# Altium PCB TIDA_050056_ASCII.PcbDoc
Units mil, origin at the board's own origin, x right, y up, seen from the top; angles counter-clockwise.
Board outline 780 x 850 mil, 4 copper layers (Top Layer, Signal Layer 1, Signal Layer 2, Bottom Layer), stack 40 mil thick; 23 components, 6 nets, 30 pads, 38 vias.
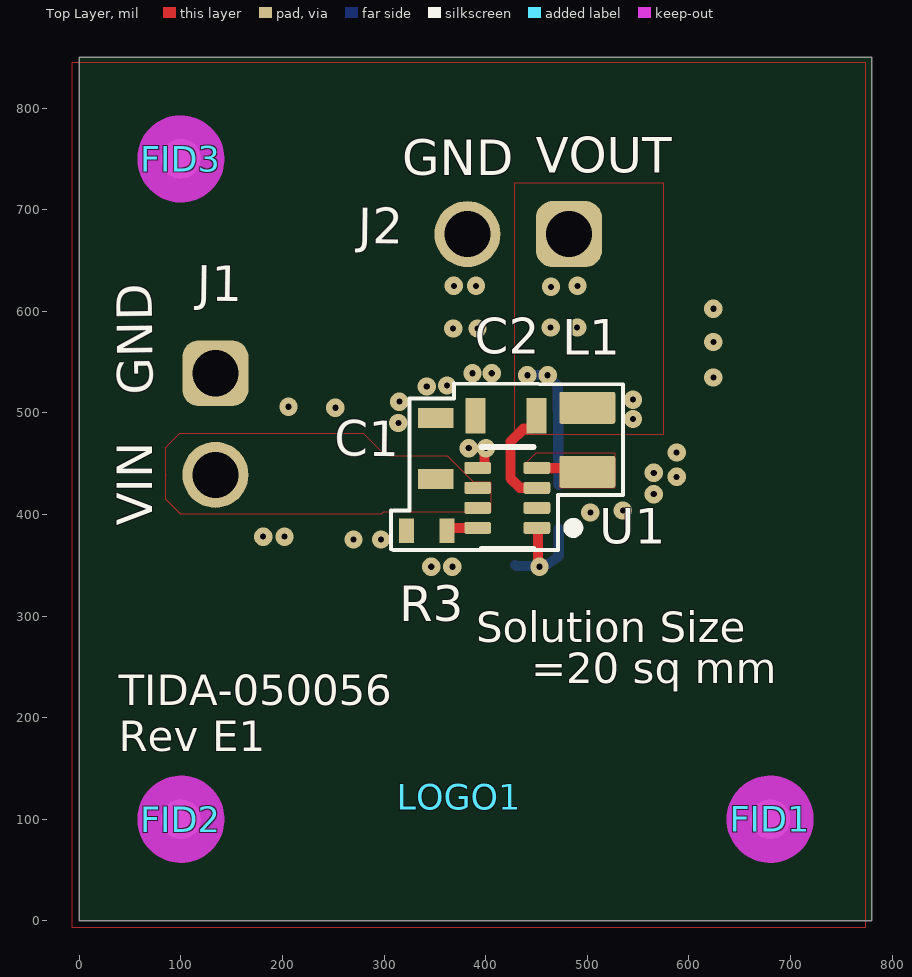
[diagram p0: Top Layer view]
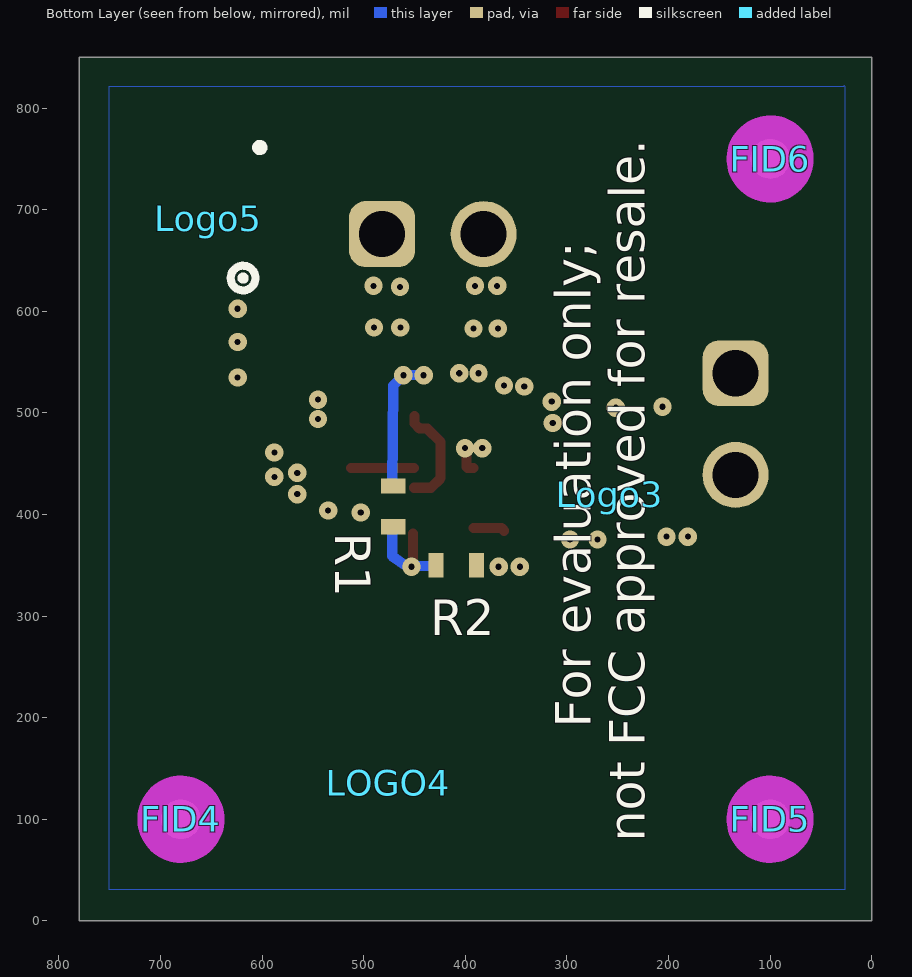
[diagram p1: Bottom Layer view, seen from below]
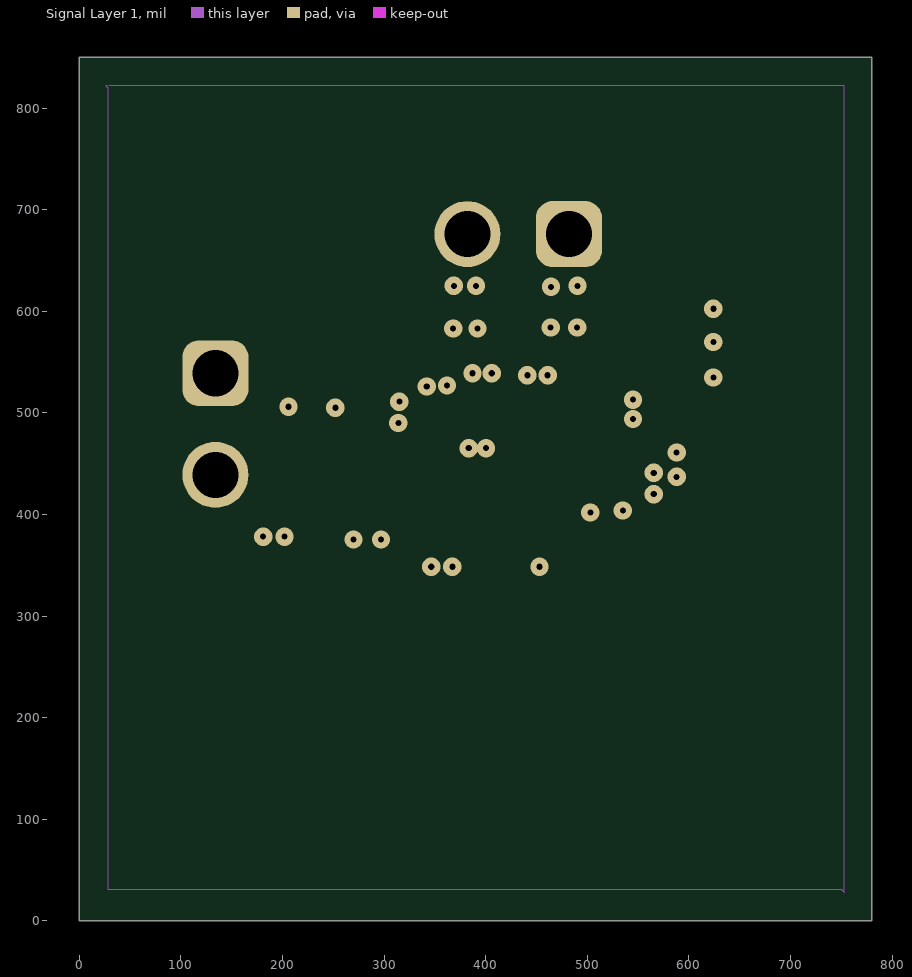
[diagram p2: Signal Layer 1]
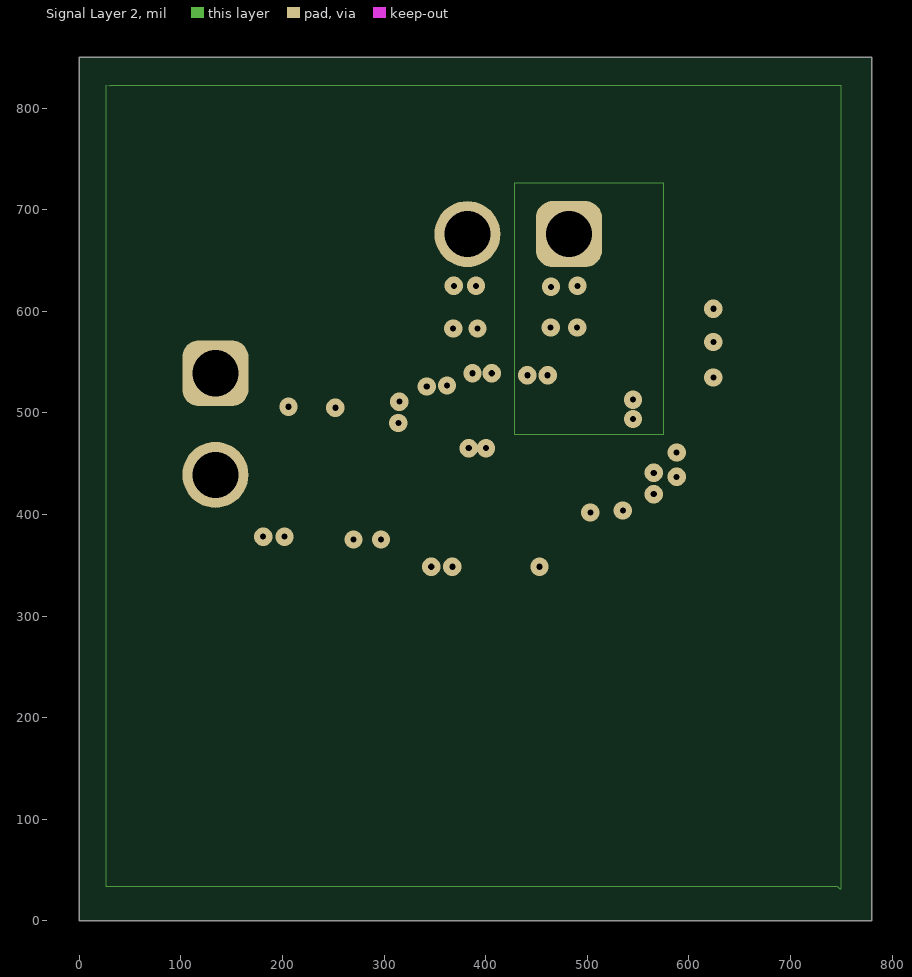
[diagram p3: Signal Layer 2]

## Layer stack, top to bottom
Top Solder: solder mask 0.4, Solder Resist, Dk 3.5
Top Layer: signal copper 1.4
Dielectric 1: prepreg 5, FR-4 High Tg, Dk 4.2
Signal Layer 1: signal copper 1.4
Dielectric 2: core 24.4, FR-4 High Tg, Dk 4.2
Signal Layer 2: signal copper 1.4
Dielectric 3: prepreg 5, FR-4 High Tg, Dk 4.2
Bottom Layer: signal copper 1.4
Bottom Solder: solder mask 0.4, Solder Resist, Dk 3.5

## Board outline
0,0 780,0 780,850 0,850

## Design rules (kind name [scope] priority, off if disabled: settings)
AcuteAngle [All] p0: scope1count=1 scope1_0_kind=Board scope1_0_value=Board scope2count=1 scope2_0_kind=Board scope2_0_value=Board commentlength=0 minimum=4.50000000000000E+0001
AcuteAngle [All] p1: minimum=4.50000000000000E+0001 checktracksonly=FALSE
AssemblyTestPointUsage [All] p0: scope1count=1 scope1_0_kind=Board scope1_0_value=Board scope2count=1 scope2_0_kind=Board scope2_0_value=Board commentlength=0
AssemblyTestPointUsage [All] p1: valid=2
AssemblyTestpoint [All] p0: scope1count=1 scope1_0_kind=Board scope1_0_value=Board scope2count=1 scope2_0_kind=Board scope2_0_value=Board commentlength=0
BoardOutlineClearance BoardOutlineClearance_MountingHoles [All] p0 off: scope1count=1 scope1_0_kind=Board scope1_0_value=Board scope2count=1 scope2_0_kind=Board scope2_0_value=Board commentlength=86 gap=40 // Protel DXP Scope 1 Expression Was: OnCopper and InComponentClass('Mounting Holes')
BoardOutlineClearance BoardOutlineClearance_Poly [All] p0 off: scope1count=1 scope1_0_kind=Board scope1_0_value=Board scope2count=1 scope2_0_kind=Board scope2_0_value=Board commentlength=58 gap=25 // Protel DXP Scope 1 Expression Was: OnCopper and IsPoly
BoardOutlineClearance [All] p0 off: scope1count=1 scope1_0_kind=Board scope1_0_value=Board scope2count=1 scope2_0_kind=Board scope2_0_value=Board commentlength=172 gap=40 // Protel DXP Scope 1 Expression Was: OnCopper and Not InComponentClass('Logo') and not InComponentClass('FiducialMark') and not InRegion(1000,500,4000,800) and not InPoly
BoardOutlineClearance BoardOutlineClearance_MountingHoles [OnCopper and InComponentClass('Mounting Holes')] p1: gap=40 ignorepadtopadclearanceinfootprint=FALSE
BoardOutlineClearance BoardOutlineClearance_Poly [OnCopper and IsPoly] p2: gap=25 ignorepadtopadclearanceinfootprint=FALSE
BoardOutlineClearance [OnCopper and Not InComponentClass('Logo') and not InComponentClass('FiducialMark') and not InRegion(1000,500,4000,800) and not InPoly] p3: gap=40 ignorepadtopadclearanceinfootprint=FALSE
Clearance Clearance_Keepouts [All] p0 off: scope1count=1 scope1_0_kind=Board scope1_0_value=Board scope2count=1 scope2_0_kind=Board scope2_0_value=Board commentlength=99 gap=0 // Protel DXP Scope 2 Expression Was: ((IsTrack Or IsArc) And Not InPoly) And IsFree and IsKeepOut
Clearance Clearance_Poly [All] p0 off: scope1count=1 scope1_0_kind=Board scope1_0_value=Board scope2count=1 scope2_0_kind=Board scope2_0_value=Board commentlength=48 gap=10 // Protel DXP Scope 1 Expression Was: InPolygon
Clearance Clearance_FiducialMark [All] p0 off: scope1count=1 scope1_0_kind=Board scope1_0_value=Board scope2count=1 scope2_0_kind=Board scope2_0_value=Board commentlength=81 gap=0 // Protel DXP Scope 2 Expression Was: IsPad and InComponentClass('FiducialMark')
Clearance [All] p0: scope1count=1 scope1_0_kind=Board scope1_0_value=Board scope2count=1 scope2_0_kind=Board scope2_0_value=Board commentlength=0 gap=7.87
Clearance Clearance_Keepouts [((IsTrack Or IsArc) And Not InPoly) And IsFree and IsKeepOut vs ((IsTrack Or IsArc) And Not InPoly) And IsFree and IsKeepOut] p1: gap=0 ignorepadtopadclearanceinfootprint=FALSE
Clearance Clearance_Poly [InPolygon] p2: gap=10 ignorepadtopadclearanceinfootprint=FALSE
Clearance Clearance_FiducialMark [IsKeepOut and InComponentClass('FiducialMark') vs IsPad and InComponentClass('FiducialMark')] p3: gap=0 ignorepadtopadclearanceinfootprint=FALSE
Clearance [All] p4: gap=7.87 ignorepadtopadclearanceinfootprint=FALSE
ComponentClearance ComponentClearance_MountingHoles_FiducialMarks [All] p0: scope1count=1 scope1_0_kind=ComponentClass scope1_0_value="Mounting Holes" scope2count=1 scope2_0_kind=ComponentClass scope2_0_value=FiducialMark commentlength=0 gap=50 collisioncheckmode=3
ComponentClearance ComponentClearance_Shunt [All] p0: scope1count=1 scope1_0_kind=ComponentClass scope1_0_value=Header scope2count=1 scope2_0_kind=ComponentClass scope2_0_value=Shunt commentlength=0 gap=0 collisioncheckmode=3
ComponentClearance ComponentClearance_Logo [All] p0: scope1count=1 scope1_0_kind=ComponentClass scope1_0_value=Logo scope2count=1 scope2_0_kind=Board scope2_0_value=Board commentlength=0 gap=30 collisioncheckmode=3
ComponentClearance ComponentClearance_ScrewToNut [All] p0 off: scope1count=1 scope1_0_kind=Board scope1_0_value=Board scope2count=1 scope2_0_kind=Board scope2_0_value=Board commentlength=71 gap=5 collisioncheckmode=3 // Protel DXP Scope 2 Expression Was: (HasFootprint('Keystone_1902C'))
ComponentClearance ComponentClearance_MountingHoles [All] p0: scope1count=1 scope1_0_kind=ComponentClass scope1_0_value="Mounting Holes" scope2count=1 scope2_0_kind=Board scope2_0_value=Board commentlength=0 gap=100 collisioncheckmode=3
ComponentClearance ComponentClearance_SmallPassives [All] p0 off: scope1count=1 scope1_0_kind=Board scope1_0_value=Board scope2count=1 scope2_0_kind=Board scope2_0_value=Board commentlength=508 gap=14.96 collisioncheckmode=3 // Protel DXP Scope 2 Expression Was: HasFootprint('0201*') or HasFootprint('0402*') or HasFootprint('0508') or HasFootprint('0603*') or HasFootprint('0612') or HasFootprint('0805*') or HasFootprint('0815*') or HasFootprint('0830*') or HasFootprint('1206*') or HasFootprint('1210*') or HasFootprint('1808*') or HasFootprint('1812*') or HasFootprint('1825*') or HasFootprint('2010*') or HasFootprint('2220*') or HasFootprint('2225*') or HasFootprint('2512*') or HasFootprint('2728*') or HasFootprint('3518*')
ComponentClearance ComponentClearance_THtoSMT [All] p0 off: scope1count=1 scope1_0_kind=Board scope1_0_value=Board scope2count=1 scope2_0_kind=Board scope2_0_value=Board commentlength=53 gap=30 collisioncheckmode=3 // Protel DXP Scope 2 Expression Was: IsSMTComponent
ComponentClearance ComponentClearance_THtoTH [All] p0 off: scope1count=1 scope1_0_kind=Board scope1_0_value=Board scope2count=1 scope2_0_kind=Board scope2_0_value=Board commentlength=54 gap=30 collisioncheckmode=3 // Protel DXP Scope 2 Expression Was: IsThruComponent
ComponentClearance [All] p0: scope1count=1 scope1_0_kind=Board scope1_0_value=Board scope2count=1 scope2_0_kind=Board scope2_0_value=Board commentlength=0 gap=20 collisioncheckmode=3
ComponentClearance ComponentClearance_MountingHoles_FiducialMarks [InComponentClass('Mounting Holes') vs InComponentClass('FiducialMark')] p1: gap=50 collisioncheckmode=3 verticalgap=10 showdistances=FALSE
ComponentClearance ComponentClearance_Shunt [InComponentClass('Header') vs InComponentClass('Shunt')] p2: gap=0 collisioncheckmode=3 verticalgap=0 showdistances=FALSE
ComponentClearance ComponentClearance_Logo [InComponentClass('Logo')] p3: gap=30 collisioncheckmode=3 verticalgap=10 showdistances=FALSE
ComponentClearance ComponentClearance_ScrewToNut [(HasFootprint('NY PMS 440 0025 PH')) vs (HasFootprint('Keystone_1902C'))] p4: gap=5 collisioncheckmode=3 verticalgap=10 showdistances=FALSE
ComponentClearance ComponentClearance_MountingHoles [InComponentClass('Mounting Holes')] p5: gap=100 collisioncheckmode=3 verticalgap=100000 showdistances=FALSE
ComponentClearance ComponentClearance_SmallPassives [HasFootprint('0201*') or HasFootprint('0402*') or HasFootprint('0508') or HasFootprint('0603*') or HasFootprint('0612') or HasFootprint('0805*') or HasFootprint('0815*') or HasFootprint('0830*') or HasFootprint('1206*') or HasFootprint('1210*') or HasFootprint('1808*') or HasFootprint('1812*') or HasFootprint('1825*') or HasFootprint('2010*') or HasFootprint('2220*') or HasFootprint('2225*') or HasFootprint('2512*') or HasFootprint('2728*') or HasFootprint('3518*') vs HasFootprint('0201*') or HasFootprint('0402*') or HasFootprint('0508') or HasFootprint('0603*') or HasFootprint('0612') or HasFootprint('0805*') or HasFootprint('0815*') or HasFootprint('0830*') or HasFootprint('1206*') or HasFootprint('1210*') or HasFootprint('1808*') or HasFootprint('1812*') or HasFootprint('1825*') or HasFootprint('2010*') or HasFootprint('2220*') or HasFootprint('2225*') or HasFootprint('2512*') or HasFootprint('2728*') or HasFootprint('3518*')] p6: gap=14.96 collisioncheckmode=3 verticalgap=10 showdistances=FALSE
ComponentClearance ComponentClearance_THtoSMT [IsThruComponent vs IsSMTComponent] p7: gap=30 collisioncheckmode=3 verticalgap=30 showdistances=FALSE
ComponentClearance ComponentClearance_THtoTH [IsThruComponent vs IsThruComponent] p8: gap=30 collisioncheckmode=3 verticalgap=30 showdistances=FALSE
ComponentClearance [All] p9: gap=20 collisioncheckmode=3 verticalgap=10 showdistances=FALSE
DiffPairsRouting [All] p0: scope1count=1 scope1_0_kind=Board scope1_0_value=Board scope2count=1 scope2_0_kind=Board scope2_0_value=Board commentlength=0
DiffPairsRouting [All] p1: maxlimit=100 minlimit=10 mostfreqgap=10 toplayer_minwidth=15 toplayer_maxwidth=15 toplayer_prefwidth=15 midlayer1_minwidth=15 midlayer1_maxwidth=15 midlayer1_prefwidth=15 midlayer2_minwidth=15 midlayer2_maxwidth=15 midlayer2_prefwidth=15 bottomlayer_minwidth=15 bottomlayer_maxwidth=15 bottomlayer_prefwidth=15 maxuncoupledlength=1000
FabricationTestPointUsage TestPointUsage [All] p0: scope1count=1 scope1_0_kind=Board scope1_0_value=Board scope2count=1 scope2_0_kind=Board scope2_0_value=Board commentlength=0 valid=2 allowmultiple=FALSE
FabricationTestPointUsage TestPointUsage [All] p1: valid=2 allowmultiple=FALSE
FabricationTestpoint Testpoint [All] p0: scope1count=1 scope1_0_kind=Board scope1_0_value=Board scope2count=1 scope2_0_kind=Board scope2_0_value=Board commentlength=0 side=3 testpointundercomponent=TRUE minsize=40 maxsize=100 preferedsize=60 minholesize=0 maxholesize=40 preferedholesize=32 testpointgrid=1
FabricationTestpoint Testpoint [All] p1: side=3 testpointundercomponent=TRUE minsize=40 maxsize=100 preferedsize=60 minholesize=0 maxholesize=40 preferedholesize=32 testpointgrid=1 allowsidetop=TRUE allowsidebottom=TRUE usegrid=TRUE gridtolerance=0.01
FanoutControl Fanout_LCC [All] p0 off: scope1count=1 scope1_0_kind=Board scope1_0_value=Board scope2count=1 scope2_0_kind=Board scope2_0_value=Board commentlength=69 // Protel DXP Scope 1 Expression Was: IsLCC   Fanout_LCC (Default Rule)
FanoutControl Fanout_BGA [All] p0 off: scope1count=1 scope1_0_kind=Board scope1_0_value=Board scope2count=1 scope2_0_kind=Board scope2_0_value=Board commentlength=69 // Protel DXP Scope 1 Expression Was: IsBGA   Fanout_BGA (Default Rule)
FanoutControl Fanout_SOIC [All] p0 off: scope1count=1 scope1_0_kind=Board scope1_0_value=Board scope2count=1 scope2_0_kind=Board scope2_0_value=Board commentlength=71 // Protel DXP Scope 1 Expression Was: IsSOIC   Fanout_SOIC (Default Rule)
FanoutControl Fanout_Default [All] p0: scope1count=1 scope1_0_kind=Board scope1_0_value=Board scope2count=1 scope2_0_kind=Board scope2_0_value=Board commentlength=30 // Fanout_Default (Default Rule)
FanoutControl Fanout_Small [All] p0 off: scope1count=1 scope1_0_kind=Board scope1_0_value=Board scope2count=1 scope2_0_kind=Board scope2_0_value=Board commentlength=84 // Protel DXP Scope 1 Expression Was: (CompPinCount < 5)   Fanout_Small (Default Rule)
FanoutControl Fanout_LCC [IsLCC] p1: bgadir=Out bgaviamode=Centered fanoutstyle=Auto fanoutdirection=Alternating viagrid=1 // Fanout_LCC (Default Rule)
FanoutControl Fanout_BGA [IsBGA] p2: bgadir=Out bgaviamode=Centered fanoutstyle=Auto fanoutdirection=Alternating viagrid=1 // Fanout_BGA (Default Rule)
FanoutControl Fanout_Default [All] p4: bgadir=Out bgaviamode=Centered fanoutstyle=Auto fanoutdirection=Alternating viagrid=1 // Fanout_Default (Default Rule)
FanoutControl Fanout_Small [(CompPinCount < 5)] p5: bgadir=Out bgaviamode=Centered fanoutstyle=Auto fanoutdirection=OutThenIn viagrid=1 // Fanout_Small (Default Rule)
Height [All] p0: scope1count=1 scope1_0_kind=Board scope1_0_value=Board scope2count=1 scope2_0_kind=Board scope2_0_value=Board commentlength=0
HoleSize [All] p0: scope1count=1 scope1_0_kind=Board scope1_0_value=Board scope2count=1 scope2_0_kind=Board scope2_0_value=Board commentlength=0 absolutevalues=TRUE maxlimit=251 minlimit=5.9 maxpercent=80.000 minpercent=20.000
HoleSize [All] p1: absolutevalues=TRUE maxlimit=251 minlimit=5.9 maxpercent=80.000 minpercent=20.000
HoleToHoleClearance [All] p0: scope1count=1 scope1_0_kind=Board scope1_0_value=Board scope2count=1 scope2_0_kind=Board scope2_0_value=Board commentlength=0
LayerPairs [All] p0: scope1count=1 scope1_0_kind=Board scope1_0_value=Board scope2count=1 scope2_0_kind=Board scope2_0_value=Board commentlength=0 enforce=TRUE
MinimumAnnularRing MinimumAnnularRing_ThermalPadVias [All] p0 off: scope1count=1 scope1_0_kind=Board scope1_0_value=Board scope2count=1 scope2_0_kind=Board scope2_0_value=Board commentlength=63 minimumring=5.91 // Protel DXP Scope 1 Expression Was: IsVia and InAnyComponent
MinimumAnnularRing [All] p0: scope1count=1 scope1_0_kind=Board scope1_0_value=Board scope2count=1 scope2_0_kind=Board scope2_0_value=Board commentlength=0 minimumring=6
MinimumAnnularRing MinimumAnnularRing_ThermalPadVias [IsVia and InAnyComponent] p1: minimumring=5.91
MinimumAnnularRing [All] p2: minimumring=6
MinimumSolderMaskSliver MinimumSolderMaskSliver_Logo [All] p0: scope1count=1 scope1_0_kind=ComponentClass scope1_0_value=Logo scope2count=1 scope2_0_kind=ComponentClass scope2_0_value=Logo commentlength=0
MinimumSolderMaskSliver [All] p0: scope1count=1 scope1_0_kind=Board scope1_0_value=Board scope2count=1 scope2_0_kind=Board scope2_0_value=Board commentlength=0
MinimumSolderMaskSliver MinimumSolderMaskSliver_Logo [InComponentClass('Logo') vs InComponentClass('Logo')] p1: minsoldermaskwidth=0.7
MinimumSolderMaskSliver [All] p2: minsoldermaskwidth=3.94
NetAntennae [All] p0: scope1count=1 scope1_0_kind=Board scope1_0_value=Board scope2count=1 scope2_0_kind=Board scope2_0_value=Board commentlength=0
PasteMaskExpansion [All] p0: scope1count=1 scope1_0_kind=Board scope1_0_value=Board scope2count=1 scope2_0_kind=Board scope2_0_value=Board commentlength=0 expansion=0
PlaneClearance [All] p0: scope1count=1 scope1_0_kind=Board scope1_0_value=Board scope2count=1 scope2_0_kind=Board scope2_0_value=Board commentlength=0 clearance=20
PlaneConnect [All] p0: scope1count=1 scope1_0_kind=Board scope1_0_value=Board scope2count=1 scope2_0_kind=Board scope2_0_value=Board commentlength=0 planeconnectstyle=Relief reliefexpansion=10 reliefentries=4 reliefconductorwidth=10 reliefairgap=10
PlaneConnect [All] p1: planeconnectstyle=Relief reliefexpansion=10 reliefentries=4 reliefconductorwidth=10 reliefairgap=10
PolygonConnect [All] p0: scope1count=1 scope1_0_kind=Board scope1_0_value=Board scope2count=1 scope2_0_kind=Board scope2_0_value=Board commentlength=0 connectstyle=Direct reliefconductorwidth=10 reliefentries=4 polygonreliefangle="90 Angle"
PolygonConnect PolygonConnect_R2 [All] p0 off: scope1count=1 scope1_0_kind=Board scope1_0_value=Board scope2count=1 scope2_0_kind=Board scope2_0_value=Board commentlength=140 connectstyle=Relief reliefconductorwidth=10 reliefentries=4 polygonreliefangle="90 Angle" // Protel DXP Scope 1 Expression Was: InComponent('R4') or InComponent('C3') or InComponent('R2') or InComponent('R6') or InComponent('R8')
PolygonConnect PolygonConnect_R2 [InComponent('R4') or InComponent('C3') or InComponent('R2') or InComponent('R6') or InComponent('R8')] p1: connectstyle=Relief reliefconductorwidth=10 reliefentries=4 polygonreliefangle="90 Angle" airgapwidth=10
PolygonConnect [All] p2: connectstyle=Direct reliefconductorwidth=10 reliefentries=4 polygonreliefangle="90 Angle" airgapwidth=10
RoutingCorners [All] p0: scope1count=1 scope1_0_kind=Board scope1_0_value=Board scope2count=1 scope2_0_kind=Board scope2_0_value=Board commentlength=0 cornerstyle=45-Degree minsetback=100 maxsetback=100
RoutingLayers [All] p0: scope1count=1 scope1_0_kind=Board scope1_0_value=Board scope2count=1 scope2_0_kind=Board scope2_0_value=Board commentlength=0 top layer=Automatic mid layer 1=Automatic mid layer 2=Automatic bottom layer=Automatic
RoutingPriority [All] p0: scope1count=1 scope1_0_kind=Board scope1_0_value=Board scope2count=1 scope2_0_kind=Board scope2_0_value=Board commentlength=0
RoutingTopology [All] p0: scope1count=1 scope1_0_kind=Board scope1_0_value=Board scope2count=1 scope2_0_kind=Board scope2_0_value=Board commentlength=0 topology=Shortest
RoutingVias ThermalPadVias [All] p0 off: scope1count=1 scope1_0_kind=Board scope1_0_value=Board scope2count=1 scope2_0_kind=Board scope2_0_value=Board commentlength=63 holewidth=7.87 width=19.68 viastyle="Through Hole" minholewidth=7.87 minwidth=19.68 maxholewidth=12.99 maxwidth=23.62 // Protel DXP Scope 1 Expression Was: IsVia and InAnyComponent
RoutingVias [All] p0: scope1count=1 scope1_0_kind=Board scope1_0_value=Board scope2count=1 scope2_0_kind=Board scope2_0_value=Board commentlength=0 holewidth=16 width=34 viastyle="Through Hole" minholewidth=5.9 minwidth=18 maxholewidth=40 maxwidth=65
RoutingVias ThermalPadVias [IsVia and InAnyComponent] p1: holewidth=7.87 width=19.68 viastyle="Through Hole" minholewidth=7.87 minwidth=19.68 maxholewidth=12.99 maxwidth=23.62
RoutingVias [All] p2: holewidth=16 width=34 viastyle="Through Hole" minholewidth=5.9 minwidth=18 maxholewidth=40 maxwidth=65
ShortCircuit [All] p0: scope1count=1 scope1_0_kind=Board scope1_0_value=Board scope2count=1 scope2_0_kind=Board scope2_0_value=Board commentlength=0 allowed=FALSE
SilkToBoardRegionClearance [All] p0 off: scope1count=1 scope1_0_kind=Board scope1_0_value=Board scope2count=1 scope2_0_kind=Board scope2_0_value=Board commentlength=130 // Protel DXP Scope 1 Expression Was: Not ((IsComment or IsDesignator) And (Hide <> 'False')) and not InRegion(1000,500,4000,800)
SilkToBoardRegionClearance [Not ((IsComment or IsDesignator) And (Hide <> 'False')) and not InRegion(1000,500,4000,800)] p1:
SilkToSilkClearance SilkToSilkClearance_Pb-FreeLogo [All] p0 off: scope1count=1 scope1_0_kind=Board scope1_0_value=Board scope2count=1 scope2_0_kind=Board scope2_0_value=Board commentlength=120 // Protel DXP Scope 2 Expression Was: (HasFootprint('Pb-Free_Overlay_Medium') OR HasFootprint('Pb-Free_Overlay_Small'))
SilkToSilkClearance [All] p0: scope1count=1 scope1_0_kind=Board scope1_0_value=Board scope2count=1 scope2_0_kind=Board scope2_0_value=Board commentlength=0
SilkToSilkClearance SilkToSilkClearance_Pb-FreeLogo [(HasFootprint('Pb-Free_Overlay_Medium') OR HasFootprint('Pb-Free_Overlay_Small')) vs (HasFootprint('Pb-Free_Overlay_Medium') OR HasFootprint('Pb-Free_Overlay_Small'))] p1: silktosilkclearance=0
SilkToSilkClearance [All] p2: silktosilkclearance=4
SilkToSolderMaskClearance SilkToComponentPadClearance [All] p0 off: scope1count=1 scope1_0_kind=Board scope1_0_value=Board scope2count=1 scope2_0_kind=Board scope2_0_value=Board commentlength=87 // Protel DXP Scope 1 Expression Was: (IsPad or IsFill or IsRegion) and InAnycomponent
SilkToSolderMaskClearance "Silk to Solder Mask Opening" [All] p0: scope1count=1 scope1_0_kind=Board scope1_0_value=Board scope2count=1 scope2_0_kind=Board scope2_0_value=Board commentlength=0
SilkToSolderMaskClearance SilkToComponentPadClearance [(IsPad or IsFill or IsRegion) and InAnycomponent] p1: minsilkscreentomaskgap=5 clearancetoexposedcopper=TRUE
SilkToSolderMaskClearance "Silk to Solder Mask Opening" [All] p2: minsilkscreentomaskgap=3.94 clearancetoexposedcopper=FALSE
SolderMaskExpansion [All] p0: scope1count=1 scope1_0_kind=Board scope1_0_value=Board scope2count=1 scope2_0_kind=Board scope2_0_value=Board commentlength=0 expansion=1.97
SolderMaskExpansion [All] p1: expansion=1.97 istentingtop=FALSE
UnRoutedNet [All] p0: scope1count=1 scope1_0_kind=Board scope1_0_value=Board scope2count=1 scope2_0_kind=Board scope2_0_value=Board commentlength=0
UnpouredPolygon [All] p0: scope1count=1 scope1_0_kind=Board scope1_0_value=Board scope2count=1 scope2_0_kind=Board scope2_0_value=Board commentlength=0
Width [All] p0: scope1count=1 scope1_0_kind=Board scope1_0_value=Board scope2count=1 scope2_0_kind=Board scope2_0_value=Board commentlength=0 maxlimit=100 minlimit=6 preferedwidth=10
Width [All] p1: maxlimit=100 minlimit=6 preferedwidth=10 checkconnectedcopper=TRUE
15 further rules are at their usual default settings.

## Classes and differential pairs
component class Logo: LOGO1
component class TIDA_050056_Hardware: FID1 FID2 FID3 FID4 FID5 FID6 LOGO1 Logo3 LOGO4 Logo5 SH-J1 SH-J5 ZZ1 ZZ2 ZZ3 ZZ4
component class FiducialMark: FID1 FID2 FID3 FID4 FID5 FID6
component class AssemblyNote: ZZ1 ZZ2 ZZ3 ZZ4
component class TIDA_050056: C1 C2 J1 J2 L1 R1 R2 R3 R49 U1
component class Header: J1 J2

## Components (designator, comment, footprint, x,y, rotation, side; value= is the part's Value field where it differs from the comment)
C1 "GRM188R61E106MA73D" 0603S 351,465 r90 top
C2 "GRM188R61A226ME15D" 0603S 420,497 r180 top
FID1 "Fiducial" Fiducial10-20 680,100 r0 top
FID2 "Fiducial" Fiducial10-20 100,100 r0 top
FID3 "Fiducial" Fiducial10-20 100,750 r0 top
FID4 "Fiducial" Fiducial10-20 680,100 r90 bottom
FID5 "Fiducial" Fiducial10-20 100,100 r180 bottom
FID6 "Fiducial" Fiducial10-20 100,750 r180 bottom
J1 "61300211121" WURTH_61300211121 134,489 r270 top
J2 "61300211121" WURTH_61300211121 432,676 r180 top
L1 "DFE201210U-1R5M=P2" "FP-DFE201210U-1R5M=P2_0805 (2012)-MFG" 500,473.5 r90 top
LOGO1 "Texas Instruments" TI_Symbol_Overlay_Small 374,122 r0 top
Logo3 "FCC disclaimer" FCC_disclaimer_stacked 258,420 r90 bottom
LOGO4 "CE Mark" CE_Mark_5mm 476,136 r180 bottom
Logo5 "WEEE logo" WEEE_Minimum 652.92,691 r180 bottom
R1 "CRCW0402154KFKED" 0402S 471,408 r90 bottom
R2 "CRCW040234K0FKED" 0402S 409.01,350.11 r0 bottom
R3 "CRCW040227K4FKED" 0402S 342,384 r0 top
U1 "TPS629210QDRLRQ1" DRL0008A-MFG 421.26,416.34 r180 top
ZZ1 "This Assembly Note is for PCB labels only" AssemblyNoteLabel 0,1250 r0 top
ZZ2 "These assemblies are ESD sensitive, ESD precautions shall be observed." AssemblyNote 0,1150 r0 top
ZZ3 "These assemblies must be clean and free from flux and all contaminants. Use of no clean flux is not acceptable." AssemblyNote 0,1050 r0 top
ZZ4 "These assemblies must comply with workmanship standards IPC-A-610 Class 2, unless otherwise specified." AssemblyNote 0,950 r0 top

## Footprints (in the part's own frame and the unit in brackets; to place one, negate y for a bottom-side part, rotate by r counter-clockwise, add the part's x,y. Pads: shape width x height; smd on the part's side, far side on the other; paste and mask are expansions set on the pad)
0402S [mil] "Based on C0402S footprint from PADS legacy"
  rect 15x24 smd: 1(-20,0) 2(20,0)
0603S [mil]
  rect 20x35 smd: 1(-30,0) 2(30,0)
AssemblyNote [mil] "Assembly Note"
AssemblyNoteLabel [mil] "Assembly Note for PCB Labels"
CE_Mark_5mm [mil] "Minimum text height for CE Mark"
DRL0008A-MFG [mm]
  rrect33% 0.67x0.3 smd paste+0 mask+0: 1(-0.74,0.75) 2(-0.74,0.25) 3(-0.74,-0.25) 4(-0.74,-0.75) 5(0.74,-0.75) 6(0.74,-0.25) 7(0.74,0.25) 8(0.74,0.75)
  silkscreen extent -1.78,-1.28 0.65,1.28
FCC_disclaimer_stacked [mil]
Fiducial10-20 [mm]
  round 1 smd mask+0: 1(0,0)
  Top Layer keep-out circle w1.178: c0,0 r0.5
"FP-DFE201210U-1R5M=P2_0805 (2012)-MFG" [mm]
  rrect13% 0.8x1.4 smd paste+0 mask+0: 1(-0.8,0) 2(0.8,0)
TI_Symbol_Overlay_Small [mil]
WEEE_Minimum [mil] "WEEElie bin"
  silkscreen extent 22,-71 54,74
WURTH_61300211121 [mm] "Header, 2.54mm, 2x1, TH"
  rrect50% 1.65x1.65 hole 1.15: 1(-1.27,0)
  round 1.65 hole 1.15: 2(1.27,0)

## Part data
C1: library part CMP-0007344-5, "CAP, CERM, 10 uF, 25 V, +/- 20%, X5R, 0603"
C2: library part CMP-0007324-5, "CAP, CERM, 22 uF, 10 V, +/- 20%, X5R, 0603"
FID1 FID2 FID3 FID4 FID5 FID6: library part CMP-0077181-1, "Fiducial mark.  There is nothing to buy or mount."
J1 J2: library part CMP-0054794-2, "Header, 2.54 mm, 2x1, Gold, TH"
L1: library part CMP-0093854-1, "1.5µH Shielded Wirewound Inductor 1.6A 138mOhm Max 0805 (2012 Metric)"
LOGO1: library part CMP-0074838-1, "Texas Instrument Corporate Signature"
Logo3: library part CMP-0074847-1, "FCC_disclaimer"
LOGO4: library part CMP-0074844-1
Logo5: library part CMP-0074769-1
R1: library part CMP-0026023-3, "RES, 154 k, 1%, 0.063 W, AEC-Q200 Grade 0, 0402"
R2: library part CMP-0026304-2, "RES, 34.0 k, 1%, 0.063 W, AEC-Q200 Grade 0, 0402"
R3: library part CMP-0026213-2, "RES, 27.4 k, 1%, 0.063 W, AEC-Q200 Grade 0, 0402"
U1: library part CMP-0089687-1, "3-V to 17-V, Synchronous Buck Converters in 1.6 mm x 2.1 mm SOT583 Package"
ZZ1: library part CMP-0003616-3
ZZ2: library part CMP-0077236-1
ZZ3: library part CMP-0077237-1
ZZ4: library part CMP-0077238-1

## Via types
v1: diameter 18, hole 6, Top Layer to Bottom Layer, tented both sides, 38 vias

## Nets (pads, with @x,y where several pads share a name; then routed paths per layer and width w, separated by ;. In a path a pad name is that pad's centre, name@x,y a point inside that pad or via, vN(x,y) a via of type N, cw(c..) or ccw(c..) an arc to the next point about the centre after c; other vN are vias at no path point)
GND: C1.2 C2.2 J1.1 J2.2 R2.1 R3.1 U1.5 | length 26.2
  Top Layer w10: U1.5 397.88,445.87 398.78,446.77 398.78,463.72 v1(400.32,465.26)
  other v1: 346.41,348.56 367.22,348.56 270,375.27 297.06,375.27 181,378.19 202,378.19 503,402 535,404 565.46,420 588,437 565.46,441 588,461 383.36,465.26 314,490 252,505 206,506 315,511 342,526 362,527 624.09,534.79 387,539 406,539 624.09,569.79 368,583 392,583 624.09,602.5 368.7,625 390.47,625
NetR1_1: R1.1 R2.2 U1.1 | length 99.7
  Top Layer w10: v1@451.59,350.11 U1.1@451.62,381.06
  Bottom Layer w10: R2.2 429.79,349.33 452.13,349.33 v1(452.91,348.56) ; v1@458,349 472,359 R1.1@472,386
NetR3_2: R3.2 U1.8 | length 31.5
  Top Layer w10: R3.2 362,384.31 364.5,386.81 U1.8
SW: L1.1 U1.4 | length 62.1
  Top Layer w10: U1.4 L1.1@512.46,445.87
VIN: C1.1 J1.2 U1.6 U1.7
VOUT: C2.1 J2.1 L1.2 R1.2 U1.3 | length 237.8
  Top Layer w10: C2.1 450,489.5 445,484.5 437.5,484.5 424.33,471.33 424.33,435.77 433.84,426.26 450.31,426.26 U1.3
  Bottom Layer w10: v1@441.8,537.2 460.8,537.2 v1(461,537) v1@463.14,537 ; v1@461.14,536.86 471,527 ; 471,525.14 R1.2@472,429
  other v1: 545,494 545,513 441,537 464,584 490,584 464.31,624 490.31,625
pads on no net: FID1.1 FID2.1 FID3.1 FID4.1 FID5.1 FID6.1 U1.2

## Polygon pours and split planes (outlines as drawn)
GND on Top Layer "TOP_LAYER_GND_P076" (solid, remove dead copper, pour order 76): -6.98,844.96 773.6,844.96 773.6,-6.9 -6.98,-6.9
VIN on Top Layer "TOP_LAYER_VIN_P074" (solid, remove dead copper, pour order 74): 85,438 85,466 99,480 279.44,480 301.44,458 362,458 388,432 404.86,432 404.86,402 299,402 297,400 100,400 85,415 85,439
VOUT on Top Layer "TOP_LAYER_VOUT_P064" (solid, remove dead copper, pour order 64): 427.89,479 575.46,479 575.46,726 427.9,726
SW on Top Layer "TOP_LAYER_SW_P042" (solid, remove dead copper, pour order 42): 437.94,448.94 438,440.84 472.44,440.84 472.44,426.26 527.56,426.26 527.56,460.11 449.11,460.11
GND on Signal Layer 1 "SIGNAL_LAYER_1_GND_P083" (solid, remove dead copper, pour order 83): 26.23,822 28,820.23 28,31 750,31 752.77,28.23 752.77,822 30.5,822 30,822.5
VOUT on Signal Layer 2 "SIGNAL_LAYER_2_VOUT_P087" (solid, remove dead copper, pour order 87): 427.89,479 575.46,479 575.46,726 427.9,726
GND on Signal Layer 2 "SIGNAL_LAYER_2_GND_P088" (solid, remove dead copper, pour order 88): 26.23,822 26.23,34 746,34 749,31 750,32 750,822 30.5,822 30,821.5
GND on Bottom Layer "BOTTOM_LAYER_GND_P082" (solid, remove dead copper, pour order 82): 28,821 751,821 751,31 26.23,31 26.23,821.23 27,822

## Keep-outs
Keep-Out Layer:
  text ".Layer_Name" at 577,-858.49 h60

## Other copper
Top Layer:
  text ".Layer_Name" at 577,-858.49 h60
Signal Layer 1:
  text ".Layer_Name" at 577,-857.49 h60
Signal Layer 2:
  text ".Layer_Name" at 577,-857.49 h60
Bottom Layer:
  text ".Layer_Name" at 577,-858.49 h60

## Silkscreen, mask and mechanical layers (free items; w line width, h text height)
Top Overlay:
  lines w4: 307,366 307,404 ; 309,365 471.16,365 471.09,419 535.29,419 535.29,528.13 369,529.07 369,514 325,514 ; 309,404 324.67,404 ; 325,404 325,513
  text "VOUT" at 449.26,736.34 h35
  text "GND" at 318,734 h35
  text "GND" at 73,518 h35 r90.77
  text "VIN" at 72,389 h35 r90
  text "Solution Size" at 390.48,274 h30
  text "=20 sq mm" at 445,234 h30
  text "TIDA-050056 / Rev E1" at 39,167 h30
  text ".Layer_Name" at 577,-858.49 h60
Bottom Overlay:
  text ".Layer_Name" at 577,-858.49 h60
Top Paste:
  text ".Layer_Name" at 577,-858.49 h60
Bottom Paste:
  text ".Layer_Name" at 577,-858.49 h60
Top Solder:
  text ".Layer_Name" at 577,-858.49 h60
  text ".Layer_Name" at 577,-858.49 h60
Bottom Solder:
  text ".Layer_Name" at 577,-858.49 h60
Drill Guide:
  text ".Layer_Name" at 577,-858.49 h60
M1 Board Outline:
  the board outline again, w10
  text ".Layer_Name" at 577,-858.49 h60
M2 Board Dimensions:
  rectangle: 0,-275 125,-150
  rectangle: 125,-400 500,-275
  lines w7: 0,-275 1000,-275 ; 125,-400 125,-150 ; 250,-400 250,-150 ; 500,-400 500,-150 ; 750,-400 750,-150 ; 0,-400 1000,-400 1000,-150 0,-150 0,-400
  text ".Layer_Name" at 577,-858.49 h60
M3 3D STEP Top:
  text ".Layer_Name" at 577,-858.49 h60
M4 3D STEP Bottom:
  text ".Layer_Name" at 577,-858.49 h60
M5 Assembly Top:
  lines w10: -292,-930.17 6308,-930.17 ; -292,-726.83 6310,-726.83 ; -292,-523.5 -292,-1133.5 3713,-1133.5 6310,-1133.5 6310,-523.5 -291.5,-523.5 -291.5,-1133.5 1284,-1133.5 ; 2173,-1133.5 2173,-523.5 ; 3440,-726.83 3440,-523.5 ; 4280,-726.83 4280,-523.5 ; 4902,-1140 4902,-937.17
  text "COMPONENTS MARKED 'DNP' SHOULD NOT BE POPULATED." at 1153.5,-318.5 h60
  text "ASSEMBLY VARIANT:" at 1153,-434 h60
  text ".VariantName" at 2189,-434 h60
  text "PCB VIEWED FROM TOP SIDE" at -228.5,-655.67 h60
  text "BOARD #:" at 2248,-655.67 h60
  text ".PRJ_Number" at 2793.5,-655.67 h60
  text "REV:" at 3638,-655.67 h60
  text ".PCB_Rev" at 3929.5,-655.67 h60
  text "SVN REV:" at 4476,-655.67 h60
  text ".VersionControl_RevNumber" at 4982,-655.67 h60
  text "TID #:" at 2248,-859 h60
  text ".TID" at 2793.5,-859 h60
  text "PLOT NAME =" at -228.5,-1064.34 h60
  text ".plot_File_Name" at 577,-1064.34 h60
  text "GENERATED    :" at 2250,-1064.34 h60
  text ".Print_Date" at 3119.5,-1064.34 h60
  text ".Print_Time" at 3848.5,-1064.34 h60
  text "TEXAS INSTRUMENTS" at 5113,-1064.34 h60
M6 Assembly Bottom:
  lines w10: -292.5,-727.33 6309.5,-727.33 ; -290.5,-930.67 6309.5,-930.67 ; 1115.5,-1140.5 1115.5,-937.67 ; 1737.5,-727.33 1737.5,-524 ; 2577.5,-727.33 2577.5,-524 ; 3844.5,-1134 3844.5,-524 ; 4733.5,-1134 6309,-1134 6309,-524 -292.5,-524 -292.5,-1134 2304.5,-1134 6309.5,-1134 6309.5,-524
  text "COMPONENTS MARKED 'DNP' SHOULD NOT BE POPULATED." at 6102,-318 h60
  text ".VariantName" at 5058,-434 h60
  text "ASSEMBLY VARIANT:" at 6097,-434 h60
  text ".VersionControl_RevNumber" at 1035.5,-656.17 h60
  text "SVN REV:" at 1541.5,-656.17 h60
  text ".PCB_Rev" at 2088,-656.17 h60
  text "REV:" at 2379.5,-656.17 h60
  text ".PRJ_Number" at 3224,-656.17 h60
  text "BOARD #:" at 3769.5,-656.17 h60
  text "PCB VIEWED FROM BOTTOM SIDE" at 6246,-656.17 h60
  text ".TID" at 3224,-859.5 h60
  text "TID #:" at 3769.5,-859.5 h60
  text "TEXAS INSTRUMENTS" at 904.5,-1064.84 h60
  text ".Print_Time" at 2169,-1064.84 h60
  text ".Print_Date" at 2898,-1064.84 h60
  text "GENERATED    :" at 3767.5,-1064.84 h60
  text ".plot_File_Name" at 5440.5,-1064.84 h60
  text "PLOT NAME =" at 6246,-1064.84 h60
M9 Title Sheet:
  lines w10: -491.5,1041.5 -291.5,1041.5 ; -491.5,3416.5 -291.5,3416.5 ; -491.5,5791.5 -291.5,5791.5 ; 2008.5,-1333.5 2008.5,-1133.5 ; 2008.5,7966.5 2008.5,8166.5 ; 4508.5,-1333.5 4508.5,-1133.5 ; 4508.5,7966.5 4508.5,8166.5 ; 6321,-1133.5 6321,-523.5 11303.5,-523.5 ; 7008.5,-1333.5 7008.5,-1133.5 ; 7008.5,7966.5 7008.5,8166.5 ; 9508.5,-1333.5 9508.5,-1133.5 ; 9508.5,7966.5 9508.5,8166.5 ; 11303.5,-1133.5 11303.5,-523.5 ; 11303.5,-823.5 14303.5,-823.5 ; 11303.5,-223.5 14303.5,-223.5 ; 11304.5,370.5 14304.5,370.5 ; 12008.5,-1333.5 12008.5,-1133.5 ; 12008.5,7966.5 12008.5,8166.5 ; 12808.5,-1123.5 12808.5,-523.5 ; 14303.5,-523.5 11303.5,-523.5 ; 14303.5,76.5 11303.5,76.5 ; 14308.5,66.5 14308.5,-1133.5 ; 14308.5,871 11304.5,871 11303.5,871 11303.5,370.5 11303.5,76.5 ; 14308.5,1041.5 14508.5,1041.5 ; 14308.5,3416.5 14508.5,3416.5 ; 14308.5,5791.5 14508.5,5791.5 ; 11303.5,-523.5 11303.5,76.5 ; 14308.5,-1133.5 14308.5,7966.5 -291.5,7966.5 -291.5,-1133.5 14308.5,-1133.5 ; -491.5,-1333.5 -491.5,8166.5 14508.5,8166.5 14508.5,-1333.5 -491.5,-1333.5
  text "1" at 739.84,8036.5 h70
  text "2" at 3235.5,8036.5 h70
  text "3" at 5724.84,8036.5 h70
  text "4" at 8231.51,8036.5 h70
  text "5" at 10730.5,8036.5 h70
  text "6" at 13235.5,8036.5 h70
  text "A" at -416.5,6893.5 h70
  text "A" at 14383.5,6893.5 h70
  text "B" at -416.5,4513.5 h70
  text "B" at 14383.5,4513.5 h70
  text "C" at -416.5,2138.5 h70
  text "C" at 14383.5,2138.5 h70
  text "PROJECT TITLE:" at 11343.5,277.5 h45
  text ".PRJ_Title" at 11393.5,144.17 h70
  text "DESIGNED FOR:" at 11343.5,-23.5 h45
  text ".PRJ_Customer" at 11393.5,-163.5 h70
  text "D" at -416.5,-231.5 h70
  text "D" at 14383.5,-231.5 h70
  text "FILE NAME:" at 11343.5,-323.5 h45
  text ".PCB_File_Name_No_Path" at 11393.5,-443.5 h70
  text "Texas Instruments (TI) and/or its licensors do not warrant the accuracy or completeness of this specification" at 6374,-605.34 h45
  text "ENGINEER:" at 11343.5,-613.5 h45
  text "LAYOUT BY:" at 12848.5,-613.5 h45
  text "or any information contained therein. TI and/or its licensors do not warrant that this design will meet" at 6329.01,-718 h45
  text ".PRJ_Engineer" at 11393.5,-768.49 h70
  text ".PCB_Layout" at 12899,-768.49 h70
  text "the specifications, will be suitable for your application or fit for any particular purpose, or will operate in" at 6329.01,-830.67 h45
  text ".Layer_Name" at 577,-858.49 h60
  text "ALTIUM DESIGNER VERSION:" at 12848.5,-923.5 h45
  text "an implementation. TI and/or its licensors do not warrant that the design is production worthy. You should" at 6329.01,-943.33 h45
  text "completely validate and test your design implementation to confirm the system functionality for your application." at 6374,-1056 h45
  text ".print_Scale" at 11393.5,-1056.83 h70
  text ".Application_BuildNumber" at 12899,-1056.83 h70
  text "1" at 739.84,-1263.5 h70
  text "2" at 3235.5,-1263.5 h70
  text "3" at 5724.84,-1263.5 h70
  text "4" at 8231.51,-1263.5 h70
  text "5" at 10730.5,-1263.5 h70
  text "6" at 13235.5,-1263.5 h70
M10 Fab Notes:
  drawing of 189 lines, arcs and shapes, not listed
  text "DESIGN INFORMATION" at 12382.02,6356.17 h60
  text "MIN. TRACK WIDTH:" at 11737.46,6224.05 h60
  text "10" at 12833.7,6224.05 h60
  text "MIL" at 12988.46,6224.05 h60
  text "MIN. CLEARANCE:" at 11737.46,6099.92 h60
  text "MIL" at 12988.46,6099.92 h60
  text "7.874" at 12679,6099 h60
  text "MIN. VIA PAD SIZE:" at 11737.46,5975.8 h60
  text "18" at 12803.71,5975.8 h60
  text "MIL" at 12988.46,5975.8 h60
  text "0.05mm (2MIL)" at 12432.46,5845.9 h60
  text "MINIMUM ANNULAR RING" at 11408.23,5837.67 h60
  text "EXTERNAL" at 13140.46,5837.67 h60
  text "PER" at 11608.23,5727.55 h60
  text "IPC-D-275 CLASS 2 LEVEL C" at 11828.23,5727.54 h60
  text "MIL, HOLES" at 13316.46,5627.07 h60
  text "+/-" at 12924,5618.48 h60
  text "+/-" at 13778,5618.48 h60
  text "REGISTRATION TOLERANCES:" at 11408.23,5617.42 h60
  text "METAL" at 12608,5617.42 h60
  text "5" at 13184.2,5617.42 h60
  text "3" at 14017.2,5617.42 h60
  text "MIL" at 14133.46,5617.42 h60
  text "HOLE SIZE TOLERANCE (UNLESS OTHERWISE SPECIFIED):" at 11408.23,5519.1 h60
  text "+/-" at 13778,5516.23 h60
  text "3" at 14017.2,5515.17 h60
  text "MIL" at 14133.46,5515.17 h60
  text "MATERIAL:" at 11333.46,5377.52 h60
  text "FR-4 High Tg" at 12319.9,5249 h60
  text "X" at 12175.46,5241.01 h60
  text "FR-408" at 11754.46,5236.49 h60
  text "OTHER" at 13242.46,5236.49 h60
  text "40 MIL (1.0mm) +/-10%" at 12074.56,5093.46 h60
  text "X" at 11954.46,5091.01 h60
  text "THICKNESS:" at 11408.23,5085.24 h60
  text "OTHER" at 13359.46,5085.24 h60
  text "TOLERANCE:" at 11408.23,4946.92 h60
  text "X" at 12256.46,4946.92 h60
  text "ANSI IPC-6012 TYPE 3 CLASS 2" at 12434.48,4946.92 h60
  text "OTHER +/-" at 12434.46,4802.73 h60
  text "BOW & TWIST:" at 11408.23,4657.54 h60
  text "X" at 12256.46,4657.54 h60
  text "ANSI IPC-6012 TYPE 3 CLASS 2" at 12434.48,4657.54 h60
  text "OTHER +/-" at 12434.46,4510.85 h60
  text "DRILLING:" at 11333.46,4380.23 h60
  text "NC_DRILL FILES" at 13094.46,4275.04 h60
  text "REFERENCE:" at 11408.23,4271.1 h60
  text "X" at 12065.46,4271.01 h60
  text "AS SHOWN" at 12243.46,4271.1 h60
  text "X" at 12966.46,4271.1 h60
  text "OTHER" at 13392.46,4128.85 h60
  text "PTH COPPER THICKNESS:" at 11407.91,4125.32 h60
  text "X" at 12547.14,4125.32 h60
  text "20-30 um" at 12675.14,4125.32 h60
  text "BOARD FINISH:" at 11333.46,3977.73 h60
  text "SILKSCREEN:" at 11488.68,3867.6 h60
  text "X" at 12446.46,3867.6 h60
  text "TOP" at 12563.46,3867.6 h60
  text "X" at 12955.67,3867.83 h60
  text "BOTTOM" at 13074.46,3867.6 h60
  text "SILKSCREEN COLOR:" at 11488.68,3712.41 h60
  text "X" at 12445.46,3712.41 h60
  text "WHITE" at 12563.46,3712.41 h60
  text "OTHER" at 13074.46,3712.41 h60
  text "X" at 12576.46,3568.96 h60
  text "GREEN" at 12694.46,3568.96 h60
  text "OTHER" at 13312.46,3568.96 h60
  text "SOLDER RESIST COLOR:" at 11488.68,3562.1 h60
  text "X" at 12576.46,3414.71 h60
  text "MATTE" at 12694.46,3414.71 h60
  text "SEMI-GLOSS" at 13312,3414.07 h60
  text "IMMERSION GOLD (ENIG)" at 12394.46,3241.94 h60
  text "ENEPIG" at 13732,3234.72 h60
  text "SURFACE FINISH:" at 11333.46,3233.72 h60
  text "X" at 12216.46,3233.72 h60
  text "IMM. TIN/SILVER OR EQUIV" at 11663,3096.4 h60
  text "OTHER" at 13094.46,3092.47 h60
  text "ARRAY/PANEL:" at 11333.46,2937.09 h60
  text "CUT AND TRIM PER M1 BOARD OUTLINE" at 12394.46,2928.87 h60
  text "N.C. ROUTE" at 12394.46,2792.9 h60
  text "X" at 13082.46,2792.9 h60
  text "V. SCORE" at 13260.46,2792.9 h60
  text "CERTIFICATION:" at 11333.46,2663.77 h60
  text "MATERIALS AND WORKMANSHIP FOR ALL PCBS" at 12058.46,2663.77 h60
  text "TO MEET OR EXCEED THE REQUIREMENTS OF:" at 12058.46,2569.71 h60
  text "X" at 11695.97,2441.08 h60
  text "ANSI IPC-A-600F CLASS ->" at 11823.96,2441.08 h60
  text "X" at 13471.97,2441.08 h60
  text "2" at 13581.96,2441.08 h60
  text "1" at 13266.96,2439.58 h60
  text "3" at 13935.96,2439.58 h60
  text "X" at 12507.97,2293.39 h60
  text "RoHS" at 12635.96,2293.39 h60
  text "OTHER" at 13280.36,2293.39 h60
  text "PER ORDER" at 13677.42,2293.39 h60
  text "ALL BOARDS MUST MEET OR EXCEED UL94-V0 REQUIREMENTS." at 11361,2139.57 h60
  text "PCB MUST BEAR THE UL94V-0 UL REGISTERED MATERIAL ID NUMBER" at 11361,2023.5 h60
  text "ADDITIONAL REQUIREMENTS:" at 11333.46,1854.08 h60
  text "MICROSECTION:" at 11408.23,1746.95 h60
  text "YES" at 12313.96,1746.95 h60
  text "REQUIRED" at 13175.46,1602.62 h60
  text "BARE BOARD ELEC. TEST:" at 11408.23,1599.76 h60
  text "NONE" at 12713.96,1599.76 h60
  text "X" at 13057.46,1599.76 h60
  text "PER ORDER" at 13767.46,1599.76 h60
  text "XX MIL VIAS REQUIRE NON-CONDUCTIVE FILL AND PLANARIZE" at 11576.38,1394.82 h59
  text "XX MIL VIAS REQUIRE CONDUCTIVE FILL AND PLANARIZE" at 11584.38,1290.84 h60
  text "OUTER XX MIL TRACES REQUIRE 50 OHM SINGLE-ENDED IMPEDANCE" at 11583.39,1127.46 h58
  text "LAYER 2 & 3 (INNER LAYERS) XX MIL WIDE, XX MIL SPACE / TRACES REQUIRE 100 OHM DIFFERENTIAL IMPEDANCE" at 11575.39,891.74 h60
  text ".Layer_Name" at 577,-858.49 h60
M11 Gerber Information:
  lines w10: -292,-930.17 6308,-930.17 ; -292,-726.83 6310,-726.83 ; -292,-523.5 -292,-1133.5 3713,-1133.5 6310,-1133.5 6310,-523.5 -291.5,-523.5 -291.5,-1133.5 1284,-1133.5 ; 2173,-1133.5 2173,-523.5 ; 3440,-726.83 3440,-523.5 ; 4280,-726.83 4280,-523.5 ; 4902,-1140 4902,-937.17
  text "ALL ARTWORK VIEWED FROM TOP SIDE" at -228.5,-655.67 h60
  text "BOARD #:" at 2248,-655.67 h60
  text ".PRJ_Number" at 2793.5,-655.67 h60
  text "REV:" at 3638,-655.67 h60
  text ".PCB_Rev" at 3929.5,-655.67 h60
  text "SVN REV:" at 4476,-655.67 h60
  text ".VersionControl_RevNumber" at 4982,-655.67 h60
  text "LAYER NAME =" at -228.5,-858.49 h60
  text "TID #:" at 2248,-859 h60
  text ".TID" at 2793.5,-859 h60
  text "PLOT NAME =" at -228.5,-1064.34 h60
  text ".plot_File_Name" at 577,-1064.34 h60
  text "GENERATED    :" at 2250,-1064.34 h60
  text ".Print_Date" at 3119.5,-1064.34 h60
  text ".Print_Time" at 3848.5,-1064.34 h60
  text "TEXAS INSTRUMENTS" at 5113,-1064.34 h60
M12 Stackup:
  drawing of 295 lines, arcs and shapes, not listed
  text "Layer" at 9792.2,7868.01 h60
  text "Name" at 10202.11,7868.01 h60
  text "Material" at 11141.85,7868.01 h60
  text "Thickness" at 12001.62,7868.01 h60
  text "Constant" at 12651.45,7868.01 h60
  text "Board Layer Stack" at 13221.31,7868.01 h60
  text "Top Overlay" at 10202.11,7748.01 h60
  text "Top Solder" at 10202.11,7628.01 h60
  text "Solder Resist" at 11141.85,7628.01 h60
  text "0.40mil" at 12001.62,7628.01 h60
  text "3.5" at 12651.45,7628.01 h60
  text "1" at 9792.2,7508.01 h60
  text "Top Layer" at 10202.11,7508.01 h60
  text "1.40mil" at 12001.62,7508.01 h60
  text "Dielectric 1" at 10202.11,7388.01 h60
  text "FR-4 High Tg" at 11141.85,7388.01 h60
  text "5.00mil" at 12001.62,7388.01 h60
  text "4.2" at 12651.45,7388.01 h60
  text "2" at 9792.2,7268.01 h60
  text "Signal Layer 1" at 10202.11,7268.01 h60
  text "1.40mil" at 12001.62,7268.01 h60
  text "Dielectric 2" at 10202.11,7148.01 h60
  text "FR-4 High Tg" at 11141.85,7148.01 h60
  text "24.40mil" at 12001.62,7148.01 h60
  text "4.2" at 12651.45,7148.01 h60
  text "3" at 9792.2,7028.01 h60
  text "Signal Layer 2" at 10202.11,7028.01 h60
  text "1.40mil" at 12001.62,7028.01 h60
  text "Dielectric 3" at 10202.11,6908.01 h60
  text "FR-4 High Tg" at 11141.85,6908.01 h60
  text "5.00mil" at 12001.62,6908.01 h60
  text "4.2" at 12651.45,6908.01 h60
  text "4" at 9792.2,6788.01 h60
  text "Bottom Layer" at 10202.11,6788.01 h60
  text "1.40mil" at 12001.62,6788.01 h60
  text "Bottom Solder" at 10202.11,6668.01 h60
  text "Solder Resist" at 11141.85,6668.01 h60
  text "0.40mil" at 12001.62,6668.01 h60
  text "3.5" at 12651.45,6668.01 h60
  text "Bottom Overlay" at 10202.11,6548.01 h60
  text ".Layer_Name" at 577,-858.49 h60
M13 Component Bodies Top:
  text ".Layer_Name" at 577,-858.49 h60
M14 Component Bodies Bottom:
  text ".Layer_Name" at 577,-858.49 h60
M15 Courtyards Top:
  text ".Layer_Name" at 577,-858.49 h60
M16 Courtyards Bottom:
  text ".Layer_Name" at 577,-858.49 h60
Drill Drawing:
  lines w10: 999.92,531 1055.17,531 1027.55,475.74 999.92,531 ; 999.92,600.06 1027.55,613.88 1055.17,600.06 1041.36,627.69 1055.17,655.32 1027.55,641.5 999.92,655.32 1013.73,627.69 999.92,600.06
  lines w12: 949.83,438.45 4181.32,438.45 ; 949.83,687.09 4181.32,687.09 ; 1287.69,314.13 1287.69,811.41 ; 1619.69,314.13 1619.69,811.41 ; 2256.26,314.13 2256.26,811.41 ; 2515.4,314.13 2515.4,811.41 ; 2890.55,314.13 2890.55,811.41 ; 3614.88,314.13 3614.88,811.41 ; 949.83,314.13 4181.32,314.13 4181.32,811.41 949.83,811.41 949.83,314.13
  text "Symbol" at 1024.42,724.38 h72
  text "Quantity" at 1324.99,724.38 h72
  text "Finished Hole Size" at 1656.99,724.38 h72
  text "Plated" at 2293.55,724.38 h72
  text "Hole Type" at 2552.69,724.38 h72
  text "Drill Layer Pair" at 2927.85,724.38 h72
  text "Hole Tolerance" at 3652.18,724.38 h72
  text "38" at 1324.99,600.06 h60
  text "6.00mil (0.152mm)" at 1656.99,600.06 h60
  text "PTH" at 2293.55,600.06 h60
  text "Round" at 2552.69,600.06 h60
  text "Top Layer - Bottom Layer" at 2927.85,600.06 h60
  text "4" at 1324.99,475.74 h60
  text "45.28mil (1.150mm)" at 1656.99,475.74 h60
  text "PTH" at 2293.55,475.74 h60
  text "Round" at 2552.69,475.74 h60
  text "Top Layer - Bottom Layer" at 2927.85,475.74 h60
  text "42 Total" at 1324.99,351.42 h60
  text ".Layer_Name" at 577,-858.49 h60
Mechanical 17:
  text ".Layer_Name" at 577,-858.49 h60
Mechanical 18:
  text ".Layer_Name" at 577,-858.49 h60
Mechanical 19:
  text ".Layer_Name" at 577,-858.49 h60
